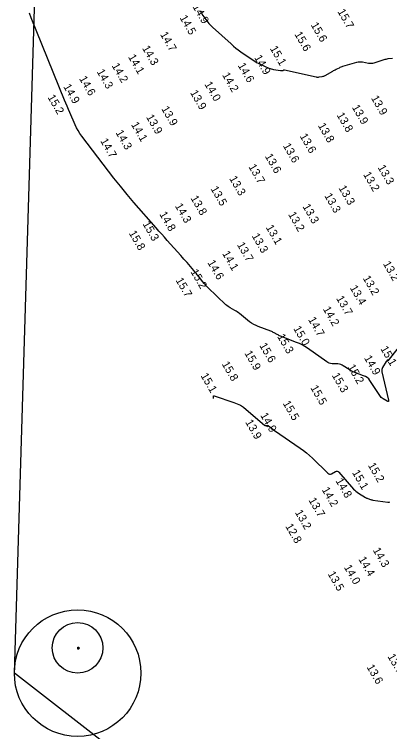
# Model space of a CAD drawing. Extents: x 988130 to 1132882, y 654656 to 841453.
# Drawn here: x 1053870.6 to 1054105.1, y 744148.2 to 744596.3 of the extents above; entities that cross this region are included whole.
import ezdxf

# ---------------------------------------------------------------- set-up
doc = ezdxf.new("R2010")
doc.units = 0
for name, color, linetype in [('V-ANNO-KEYM', 7, 'Continuous'), ('V-TOPO-MAJR', 7, 'Continuous'), ('V-TOPO-SOUN', 7, 'Continuous')]:
    doc.layers.add(name, color=color, linetype=linetype)

msp = doc.modelspace()

# ---------------------------------------------------------------- linework, layer by layer
at = {"layer": 'V-ANNO-KEYM'}
for p, q in [((1053870.57, 744184.73), (1054295.04, 758153.5)), ((1053910.17, 744200.33), (1053910.17, 744200.33)), ((1078128.69, 725426.29), (1053870.57, 744184.73))]:
    msp.add_line(p, q, dxfattribs=at)
for centre, radius in [((1053910.11, 744184.73), 39.54), ((1053910.11, 744200.55), 15.81), ((1053910.64, 744200.58), 0.474), ((1053910.64, 744200.1), 0.474)]:
    msp.add_circle(centre, radius, dxfattribs=at)
at = {"layer": 'V-TOPO-MAJR'}
for points in [[(1054110.51, 744387.9), (1054104.03, 744379.78), (1054103.96, 744379.71), (1054103.88, 744379.66), (1054103.79, 744379.63), (1054103.68, 744379.62), (1054103.26, 744379.62), (1054103.16, 744379.61), (1054103.07, 744379.58), (1054103, 744379.52), (1054102.93, 744379.44), (1054100.69, 744375.76), (1054100.37, 744375.11), (1054100.19, 744374.43), (1054100.15, 744373.73), (1054100.25, 744373.01), (1054104.4, 744355.27), (1054104.47, 744354.7), (1054104.34, 744354.4), (1054104.01, 744354.38), (1054103.5, 744354.63), (1054101.02, 744356.16), (1054100.43, 744356.58), (1054099.9, 744357.04), (1054099.42, 744357.57), (1054098.99, 744358.15), (1054092.82, 744367.5), (1054092.03, 744368.52), (1054091.11, 744369.37), (1054090.06, 744370.06), (1054088.88, 744370.58), (1054083.36, 744372.53), (1054082.41, 744372.9), (1054081.49, 744373.32), (1054080.59, 744373.81), (1054079.73, 744374.36), (1054076.18, 744376.77), (1054075.4, 744377.23), (1054074.57, 744377.57), (1054073.71, 744377.79), (1054072.81, 744377.89), (1054069.12, 744378.04), (1054068.22, 744378.14), (1054067.36, 744378.36), (1054066.55, 744378.71), (1054065.78, 744379.18), (1054053.83, 744387.67), (1054052.19, 744388.76), (1054050.48, 744389.75), (1054048.73, 744390.63), (1054046.91, 744391.4), (1054036.87, 744395.31), (1054036.36, 744395.52), (1054035.85, 744395.75), (1054035.35, 744396), (1054034.86, 744396.27), (1054032.92, 744397.37), (1054032.43, 744397.64), (1054031.93, 744397.88), (1054031.42, 744398.11), (1054030.9, 744398.32), (1054023.05, 744401.24), (1054021.6, 744401.85), (1054020.21, 744402.56), (1054018.88, 744403.38), (1054017.61, 744404.32), (1054011.24, 744409.39), (1054010.57, 744409.9), (1054009.88, 744410.38), (1054009.18, 744410.83), (1054008.46, 744411.26), (1054005.53, 744412.91), (1054004.81, 744413.35), (1054004.12, 744413.83), (1054003.47, 744414.34), (1054002.85, 744414.91), (1053991.55, 744425.74), (1053990.74, 744426.55), (1053989.95, 744427.38), (1053989.19, 744428.25), (1053988.47, 744429.14), (1053985.62, 744432.75), (1053984.9, 744433.65), (1053984.18, 744434.55), (1053983.44, 744435.43), (1053982.7, 744436.31), (1053978.51, 744441.2), (1053977.56, 744442.31), (1053976.6, 744443.4), (1053975.64, 744444.5), (1053974.67, 744445.59), (1053966.16, 744455.08), (1053964.42, 744457.03), (1053962.69, 744458.98), (1053960.96, 744460.94), (1053959.24, 744462.9), (1053945.34, 744478.76), (1053944.26, 744480.01), (1053943.19, 744481.26), (1053942.13, 744482.53), (1053941.08, 744483.8), (1053936.9, 744488.9), (1053935.86, 744490.18), (1053934.83, 744491.47), (1053933.81, 744492.77), (1053932.8, 744494.07), (1053912.72, 744520.24), (1053911.51, 744521.93), (1053910.4, 744523.68), (1053909.41, 744525.5), (1053908.53, 744527.39), (1053905.23, 744535.06), (1053904.41, 744536.97), (1053903.6, 744538.9), (1053902.8, 744540.83), (1053902.01, 744542.76), (1053881.16, 744594.24), (1053880.03, 744597.17)], [(1053986.71, 744598.51), (1053988.32, 744595.71), (1053990.16, 744593.08), (1053992.22, 744590.62), (1053994.5, 744588.34), (1054005.99, 744577.81), (1054007.46, 744576.51), (1054008.97, 744575.26), (1054010.52, 744574.07), (1054012.12, 744572.92), (1054019.74, 744567.68), (1054020.79, 744566.98), (1054021.88, 744566.34), (1054022.99, 744565.74), (1054024.14, 744565.2), (1054029.66, 744562.72), (1054030.37, 744562.43), (1054031.11, 744562.19), (1054031.85, 744562.01), (1054032.61, 744561.88), (1054036.97, 744561.3), (1054037.1, 744561.29), (1054037.23, 744561.28), (1054037.37, 744561.26), (1054037.5, 744561.26), (1054038.04, 744561.23), (1054038.17, 744561.23), (1054038.29, 744561.25), (1054038.41, 744561.29), (1054038.52, 744561.34), (1054038.97, 744561.59), (1054039.09, 744561.65), (1054039.2, 744561.68), (1054039.32, 744561.68), (1054039.45, 744561.66), (1054059.13, 744557.23), (1054059.61, 744557.15), (1054060.1, 744557.11), (1054060.58, 744557.13), (1054061.06, 744557.19), (1054063, 744557.55), (1054063.48, 744557.66), (1054063.95, 744557.81), (1054064.4, 744557.99), (1054064.83, 744558.22), (1054069.56, 744560.9), (1054070.07, 744561.19), (1054070.59, 744561.47), (1054071.11, 744561.73), (1054071.64, 744561.99), (1054073.75, 744563.01), (1054074.28, 744563.26), (1054074.82, 744563.48), (1054075.37, 744563.68), (1054075.93, 744563.86), (1054084.59, 744566.44), (1054085.48, 744566.65), (1054086.38, 744566.75), (1054087.28, 744566.74), (1054088.19, 744566.62), (1054091.83, 744565.92), (1054092.73, 744565.8), (1054093.64, 744565.79), (1054094.53, 744565.9), (1054095.42, 744566.12), (1054101.72, 744568.07), (1054102.35, 744568.25), (1054102.99, 744568.41), (1054103.63, 744568.54), (1054104.28, 744568.65), (1054106.89, 744569.03)], [(1053994.96, 744356.42), (1053994.98, 744357.67), (1053995.01, 744357.84), (1053995.08, 744357.95), (1053995.21, 744357.99), (1053995.38, 744357.96), (1054007.81, 744353.89), (1054009.89, 744353.09), (1054011.87, 744352.1), (1054013.73, 744350.91), (1054015.48, 744349.53), (1054026.94, 744339.57), (1054027.11, 744339.46), (1054027.29, 744339.38), (1054027.48, 744339.36), (1054027.68, 744339.37), (1054028.52, 744339.53), (1054028.73, 744339.55), (1054028.92, 744339.53), (1054029.11, 744339.46), (1054029.28, 744339.35), (1054031.44, 744337.64), (1054031.86, 744337.31), (1054032.29, 744336.99), (1054032.72, 744336.68), (1054033.15, 744336.38), (1054049.3, 744325.27), (1054051.31, 744323.83), (1054053.25, 744322.3), (1054055.13, 744320.7), (1054056.93, 744319.01), (1054066.56, 744309.62), (1054067.08, 744309.23), (1054067.63, 744309.05), (1054068.21, 744309.09), (1054068.81, 744309.33), (1054071.28, 744310.71), (1054071.88, 744310.95), (1054072.43, 744310.96), (1054072.95, 744310.76), (1054073.44, 744310.33), (1054082.59, 744299.75), (1054083.27, 744299.03), (1054084, 744298.36), (1054084.78, 744297.75), (1054085.61, 744297.2), (1054090.03, 744294.52), (1054090.39, 744294.31), (1054090.75, 744294.13), (1054091.13, 744293.96), (1054091.51, 744293.81), (1054093.08, 744293.27), (1054093.47, 744293.14), (1054093.87, 744293.03), (1054094.27, 744292.94), (1054094.67, 744292.87), (1054103.89, 744291.53), (1054104.32, 744291.5), (1054104.74, 744291.55), (1054105.14, 744291.68)]]:
    msp.add_lwpolyline(points, dxfattribs=at)

# ---------------------------------------------------------------- texts
at = {"layer": 'V-TOPO-SOUN'}
for s, p in [('14.9 ', (1053981.79, 744601.15)), ('15.7 ', (1054072.38, 744598.09)), ('14.5 ', (1053973.72, 744594.23)), ('15.6 ', (1054055.68, 744589.75)), ('14.7 ', (1053961.52, 744583.83)), ('15.6 ', (1054045.47, 744583.95)), ('14.3 ', (1053950.27, 744575.21)), ('15.1 ', (1054030.16, 744575.02)), ('14.1 ', (1053941.5, 744569.75)), ('14.9 ', (1054020.33, 744569.35)), ('14.2 ', (1053931.25, 744564.29)), ('14.6 ', (1054010.05, 744564.44)), ('14.3 ', (1053921.89, 744560.52)), ('14.6 ', (1053910.91, 744556.21)), ('14.2 ', (1054000.29, 744558.46)), ('14.9 ', (1053901.03, 744551.2)), ('14.0 ', (1053989.21, 744552.73)), ('13.9 ', (1053980.27, 744547.42)), ('15.2 ', (1053891.18, 744544.57)), ('13.9 ', (1054093.35, 744544.05)), ('13.9 ', (1053962.28, 744537.37)), ('13.9 ', (1054081.38, 744538.28)), ('13.9 ', (1053952.76, 744532.19)), ('13.8 ', (1054071.85, 744533.44)), ('14.1 ', (1053943.36, 744527.5)), ('13.8 ', (1054060.14, 744526.86)), ('14.3 ', (1053933.68, 744522.46)), ('13.6 ', (1054048.8, 744520.27)), ('14.7 ', (1053924.11, 744517.27)), ('13.6 ', (1054038.28, 744514.25)), ('13.6 ', (1054027.03, 744507.7)), ('13.7 ', (1054016.73, 744501.15)), ('13.3 ', (1054097.53, 744500.67)), ('13.2 ', (1054088.44, 744496.33)), ('13.3 ', (1054004.74, 744493.78)), ('13.5 ', (1053993.07, 744487.37)), ('13.3 ', (1054073.03, 744487.89)), ('13.3 ', (1054064.17, 744482.99)), ('13.8 ', (1053980.56, 744481.53)), ('14.3 ', (1053970.79, 744476.66)), ('13.3 ', (1054050.56, 744476.28)), ('14.8 ', (1053961.04, 744471.51)), ('13.2 ', (1054041.57, 744471.35)), ('15.3 ', (1053950.56, 744465.42)), ('13.1 ', (1054027.59, 744463.23)), ('15.8 ', (1053941.95, 744459.65)), ('13.3 ', (1054018.8, 744457.94)), ('13.7 ', (1054009.56, 744452.42)), ('14.1 ', (1054000.31, 744446.92)), ('14.6 ', (1053991.12, 744441.25)), ('13.2 ', (1054100.8, 744440.52)), ('15.2 ', (1053980.53, 744435.52)), ('15.7 ', (1053971.21, 744430.24)), ('13.2 ', (1054088.19, 744431.53)), ('13.4 ', (1054080.1, 744425.48)), ('13.7 ', (1054071.54, 744418.91)), ('14.2 ', (1054063.26, 744412.25)), ('14.7 ', (1054054.04, 744405.67)), ('15.0 ', (1054044.77, 744400.06)), ('15.3 ', (1054034.72, 744395.06)), ('15.6 ', (1054023.55, 744389.46)), ('15.9 ', (1054014.23, 744384.67)), ('15.1 ', (1054099.19, 744387.48)), ('14.9 ', (1054088.97, 744381.67)), ('15.8 ', (1054000.08, 744377.89)), ('15.2 ', (1054078.68, 744376.07)), ('15.1 ', (1053986.83, 744370.61)), ('15.3 ', (1054068.86, 744370.76)), ('15.5 ', (1054055.46, 744363.01)), ('15.5 ', (1054038.19, 744353.32)), ('14.9 ', (1054024.1, 744345.83)), ('13.9 ', (1054014.75, 744341.54)), ('15.2 ', (1054091.39, 744314.63)), ('15.1 ', (1054081.52, 744310.06)), ('14.8 ', (1054071.17, 744304.9)), ('14.2 ', (1054062.54, 744299.36)), ('13.7 ', (1054054.29, 744292.8)), ('13.2 ', (1054045.79, 744285.14)), ('12.8 ', (1054039.77, 744276.53)), ('14.3 ', (1054094.5, 744261.58)), ('14.4 ', (1054085.49, 744255.95)), ('14.0 ', (1054076.43, 744250.88)), ('13.5 ', (1054066.24, 744246.76)), ('13.7 ', (1054103.65, 744195.17)), ('13.6 ', (1054090.58, 744188.55))]:
    msp.add_text(s, height=5, rotation=300, dxfattribs=at).set_placement(p)

doc.saveas('drawing.dxf')
